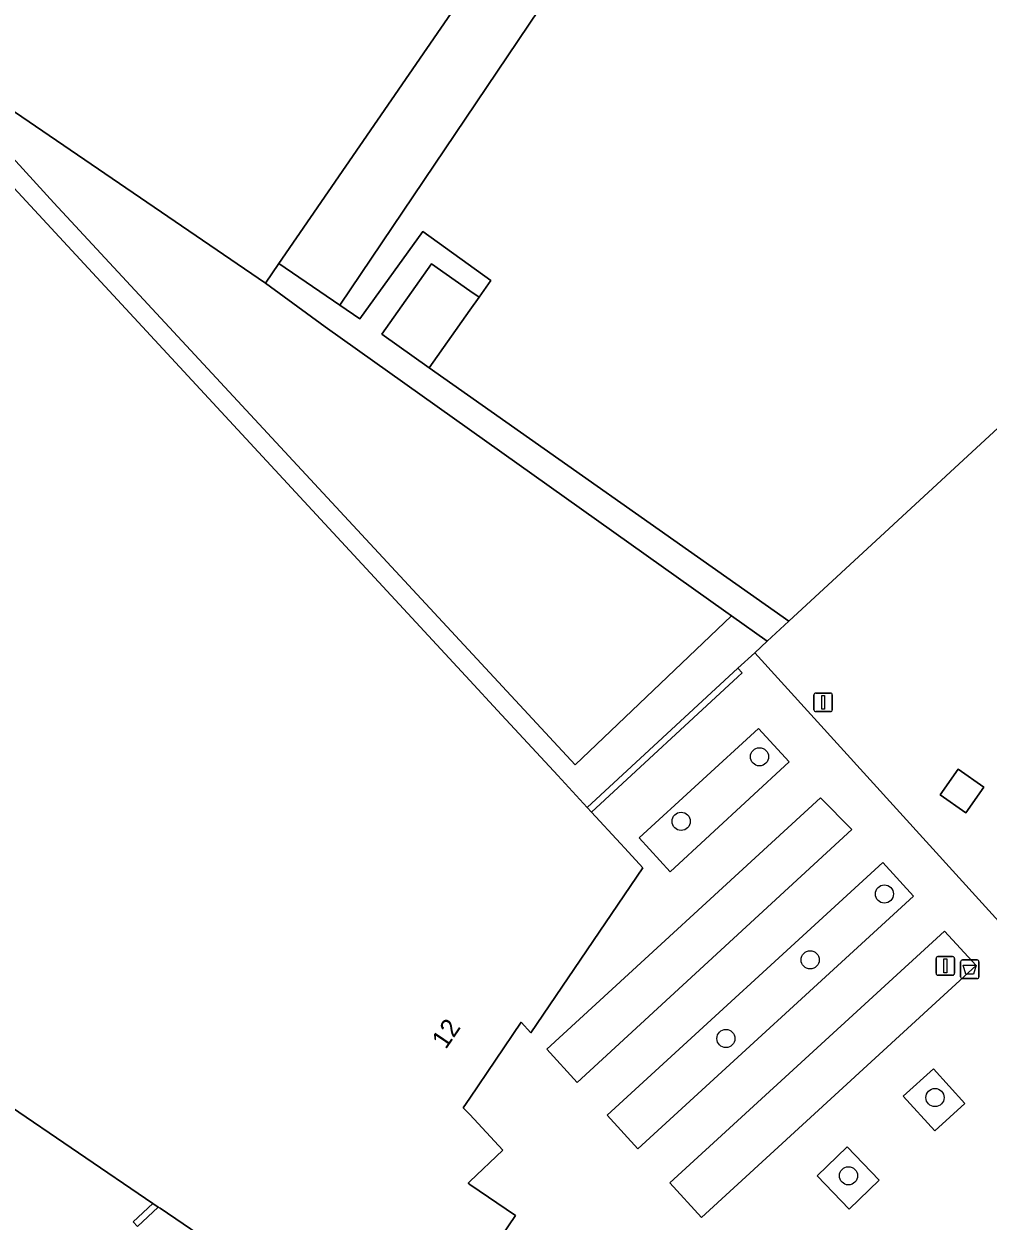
# Model space of a CAD drawing. Extents: x 157132 to 159279, y 384991 to 386650.
# Drawn here: x 158476 to 158527.9, y 385472.5 to 385536.9 of the extents above; entities that cross this region are included whole.
import ezdxf

# ---------------------------------------------------------------- set-up
doc = ezdxf.new("R2010")
doc.units = 0
for name, color, linetype in [('IMGEO_Afvalbak', 7, 'Continuous'), ('IMGEO_Boom', 7, 'Continuous'), ('IMGEO_Gemengd_bos', 7, 'Continuous'), ('IMGEO_Groenvoorziening', 7, 'Continuous'), ('IMGEO_Haag', 7, 'Continuous'), ('IMGEO_Hek', 7, 'Continuous'), ('IMGEO_Lichtmast', 7, 'Continuous'), ('IMGEO_Muur', 7, 'Continuous'), ('IMGEO_Pand', 7, 'Continuous'), ('IMGEO_Pand_nummerreeks', 7, 'Continuous'), ('IMGEO_Terreindeel_onvherhard', 7, 'Continuous'), ('IMGEO_Voetpad_open', 7, 'Continuous')]:
    doc.layers.add(name, color=color, linetype=linetype)

msp = doc.modelspace()

# ---------------------------------------------------------------- linework, layer by layer
at = {"layer": 'IMGEO_Afvalbak'}
for p, q in [((158526.419, 385485.668), (158526.419, 385486.468)), ((158526.419, 385486.468), (158526.419, 385485.668)), ((158526.519, 385486.568), (158527.309, 385486.568)), ((158527.309, 385486.568), (158526.519, 385486.568)), ((158527.409, 385486.468), (158527.409, 385485.668)), ((158527.409, 385485.668), (158527.409, 385486.468)), ((158527.309, 385485.568), (158526.519, 385485.568)), ((158526.519, 385485.568), (158527.309, 385485.568))]:
    msp.add_line(p, q, dxfattribs=at)
msp.add_lwpolyline([(158526.562, 385486.282), (158527.266, 385486.282), (158527.117, 385485.812), (158526.711, 385485.812), (158526.562, 385486.282)], dxfattribs=at)
for centre, start, end in [((158526.519, 385486.468), 90, 180), ((158526.519, 385486.468), 90, 180), ((158527.309, 385486.468), 0, 90), ((158527.309, 385486.468), 360, 90), ((158526.519, 385485.668), 180, 270), ((158526.519, 385485.668), 180, 270), ((158527.309, 385485.668), 270, 0), ((158527.309, 385485.668), 270, 0)]:
    msp.add_arc(centre, 0.1, start, end, dxfattribs=at)
at = {"layer": 'IMGEO_Boom'}
for centre in [(158515.593, 385497.506), (158511.376, 385494.032), (158522.32, 385490.12), (158518.322, 385486.575), (158513.786, 385482.342), (158525.042, 385479.165), (158520.385, 385474.954)]:
    msp.add_circle(centre, 0.489, dxfattribs=at)
at = {"layer": 'IMGEO_Gemengd_bos'}
for points in [[(158416.718, 385518.918), (158432.421, 385507.98), (158456.911, 385544.351), (158479.187, 385577.434), (158514.468, 385553.679), (158492.995, 385521.811), (158494.074, 385521.069), (158497.473, 385525.778), (158501.138, 385523.133), (158500.495, 385522.242), (158500, 385521.54), (158497.819, 385518.448), (158517.173, 385504.798), (158548.16, 385533.423), (158561.811, 385531.05), (158567.151, 385539), (158577.352, 385553.824), (158594.632, 385578.874), (158607.886, 385598.171), (158608.65, 385598.598), (158610.629, 385600.429)], [(158552.569, 385517.808), (158546.305, 385522.293), (158546.916, 385523.147), (158553.212, 385518.722), (158557.004, 385524.108), (158559.635, 385527.877), (158558.006, 385529.04), (158559.162, 385530.721), (158560.835, 385529.597), (158561.811, 385531.05), (158548.16, 385533.423), (158517.173, 385504.798), (158516.01, 385503.723), (158515.341, 385503.105), (158530.775, 385486.104), (158530.932, 385486.248)]]:
    msp.add_lwpolyline(points, dxfattribs=at)
msp.add_lwpolyline([(158526.705, 385494.493), (158525.323, 385495.454), (158526.284, 385496.837), (158527.666, 385495.876)], close=True, dxfattribs=at)
at = {"layer": 'IMGEO_Groenvoorziening'}
msp.add_lwpolyline([(158499.391, 385538.108), (158489.726, 385524.061), (158492.995, 385521.811), (158514.468, 385553.679)], dxfattribs=at)
for points in [[(158492.207, 385520.642), (158488.994, 385522.997), (158474.747, 385532.719), (158474.316, 385532.056), (158473.868, 385531.391), (158477.608, 385527.327), (158505.674, 385497.072), (158514.085, 385505.091), (158513.782, 385505.306)], [(158517.196, 385497.235), (158515.549, 385499.035), (158509.112, 385493.145), (158510.785, 385491.317)], [(158518.884, 385495.298), (158504.146, 385481.772), (158505.774, 385479.981), (158520.569, 385493.599)], [(158509.043, 385476.407), (158523.878, 385490.008), (158522.225, 385491.811), (158507.39, 385478.21)], [(158525.549, 385488.128), (158510.767, 385474.58), (158512.475, 385472.717), (158527.257, 385486.265)], [(158523.327, 385479.241), (158525.025, 385477.365), (158526.653, 385478.838), (158524.955, 385480.714)], [(158522.038, 385474.722), (158520.314, 385476.516), (158518.691, 385474.957), (158520.415, 385473.163)]]:
    msp.add_lwpolyline(points, close=True, dxfattribs=at)
at = {"layer": 'IMGEO_Haag'}
for points in [[(158523.327, 385479.241), (158525.025, 385477.365), (158526.653, 385478.838), (158524.955, 385480.714)], [(158522.038, 385474.722), (158520.314, 385476.516), (158518.691, 385474.957), (158520.415, 385473.163)]]:
    msp.add_lwpolyline(points, close=True, dxfattribs=at)
at = {"layer": 'IMGEO_Hek'}
for points in [[(158548.16, 385533.423), (158517.173, 385504.798), (158516.01, 385503.723)], [(158516.01, 385503.723), (158515.341, 385503.105)], [(158515.341, 385503.105), (158514.436, 385502.269)]]:
    msp.add_lwpolyline(points, dxfattribs=at)
at = {"layer": 'IMGEO_Lichtmast'}
for p, q in [((158518.522, 385500.037), (158518.522, 385500.837)), ((158518.522, 385500.837), (158518.522, 385500.037)), ((158518.622, 385500.937), (158519.412, 385500.937)), ((158519.412, 385500.937), (158518.622, 385500.937)), ((158519.512, 385500.837), (158519.512, 385500.037)), ((158519.512, 385500.037), (158519.512, 385500.837)), ((158519.412, 385499.937), (158518.622, 385499.937)), ((158518.622, 385499.937), (158519.412, 385499.937)), ((158525.102, 385485.852), (158525.102, 385486.652)), ((158525.102, 385486.652), (158525.102, 385485.852)), ((158525.202, 385486.752), (158525.992, 385486.752)), ((158525.992, 385486.752), (158525.202, 385486.752)), ((158526.092, 385486.652), (158526.092, 385485.852)), ((158526.092, 385485.852), (158526.092, 385486.652)), ((158525.992, 385485.752), (158525.202, 385485.752)), ((158525.202, 385485.752), (158525.992, 385485.752))]:
    msp.add_line(p, q, dxfattribs=at)
for points in [[(158518.942, 385500.812), (158519.092, 385500.812), (158519.092, 385500.062), (158518.942, 385500.062), (158518.942, 385500.812)], [(158525.522, 385486.627), (158525.672, 385486.627), (158525.672, 385485.877), (158525.522, 385485.877), (158525.522, 385486.627)]]:
    msp.add_lwpolyline(points, dxfattribs=at)
for centre, start, end in [((158518.622, 385500.837), 90, 180), ((158518.622, 385500.837), 90, 180), ((158519.412, 385500.837), 0, 90), ((158519.412, 385500.837), 360, 90), ((158518.622, 385500.037), 180, 270), ((158518.622, 385500.037), 180, 270), ((158519.412, 385500.037), 270, 0), ((158519.412, 385500.037), 270, 0), ((158525.202, 385486.652), 90, 180), ((158525.202, 385486.652), 90, 180), ((158525.992, 385486.652), 0, 90), ((158525.992, 385486.652), 360, 90), ((158525.202, 385485.852), 180, 270), ((158525.202, 385485.852), 180, 270), ((158525.992, 385485.852), 270, 0), ((158525.992, 385485.852), 270, 0)]:
    msp.add_arc(centre, 0.1, start, end, dxfattribs=at)
at = {"layer": 'IMGEO_Muur'}
for points in [[(158514.436, 385502.269), (158506.322, 385494.771)], [(158514.429, 385501.8), (158506.552, 385494.522)], [(158514.436, 385502.269), (158514.667, 385502.02), (158514.429, 385501.8)], [(158506.552, 385494.522), (158506.322, 385494.771)]]:
    msp.add_lwpolyline(points, dxfattribs=at)
msp.add_lwpolyline([(158482.939, 385473.468), (158481.877, 385472.482), (158482.108, 385472.232), (158483.227, 385473.272)], close=True, dxfattribs=at)
at = {"layer": 'IMGEO_Pand'}
for points in [[(158500, 385469.198), (158502.452, 385472.824), (158500, 385474.488), (158499.904, 385474.553), (158500, 385474.644), (158501.784, 385476.338), (158500, 385478.244), (158499.649, 385478.619), (158500, 385479.136), (158502.767, 385483.215), (158503.29, 385482.642), (158509.322, 385491.524), (158508.346, 385492.58), (158508.103, 385492.843), (158506.552, 385494.522), (158506.322, 385494.771), (158504.733, 385496.491), (158501.484, 385500), (158500, 385501.603), (158476.559, 385526.919), (158469.873, 385534.139)], [(158474.931, 385478.916), (158482.939, 385473.468), (158483.227, 385473.272), (158483.325, 385473.205), (158496.602, 385464.173)]]:
    msp.add_lwpolyline(points, dxfattribs=at)
for points in [[(158497.819, 385518.448), (158500, 385521.54), (158500.495, 385522.242), (158500, 385522.591), (158497.941, 385524.044), (158495.264, 385520.25)], [(158526.705, 385494.493), (158527.666, 385495.876), (158526.284, 385496.837), (158525.323, 385495.454)]]:
    msp.add_lwpolyline(points, close=True, dxfattribs=at)
at = {"layer": 'IMGEO_Terreindeel_onvherhard'}
msp.add_lwpolyline([(158469.587, 385558.365), (158459.253, 385543.292), (158473.559, 385533.529), (158474.747, 385532.719), (158488.994, 385522.997), (158489.726, 385524.061), (158499.391, 385538.108)], close=True, dxfattribs=at)
at = {"layer": 'IMGEO_Voetpad_open'}
for points in [[(158469.873, 385534.139), (158476.559, 385526.919), (158500, 385501.603), (158501.484, 385500), (158504.733, 385496.491), (158506.322, 385494.771), (158506.552, 385494.522), (158514.429, 385501.8), (158514.667, 385502.02), (158514.436, 385502.269), (158515.341, 385503.105), (158516.01, 385503.723), (158514.085, 385505.091), (158505.674, 385497.072), (158477.608, 385527.327), (158473.868, 385531.391)], [(158481.877, 385472.482), (158482.939, 385473.468), (158474.931, 385478.916), (158473.817, 385477.878), (158470.287, 385474.588), (158457.078, 385483.601), (158440.024, 385495.235), (158444.919, 385499.338), (158442.207, 385501.185), (158440.782, 385502.156), (158444.569, 385507.716), (158441.747, 385509.712), (158441.343, 385509.984), (158434.39, 385499.799), (158434.052, 385499.309), (158423.281, 385506.706), (158420.553, 385504.286), (158508.457, 385444.174)], [(158530.775, 385486.104), (158515.341, 385503.105), (158514.436, 385502.269), (158514.667, 385502.02), (158514.429, 385501.8), (158506.552, 385494.522), (158508.103, 385492.843), (158508.346, 385492.58), (158509.322, 385491.524), (158503.29, 385482.642), (158502.767, 385483.215), (158500, 385479.136), (158499.649, 385478.619), (158500, 385478.244), (158501.784, 385476.338), (158500, 385474.644), (158499.904, 385474.553), (158500, 385474.488), (158502.452, 385472.824), (158500, 385469.198)], [(158496.602, 385464.173), (158483.325, 385473.205), (158483.227, 385473.272), (158482.108, 385472.232)]]:
    msp.add_lwpolyline(points, dxfattribs=at)
for points in [[(158497.819, 385518.448), (158495.264, 385520.25), (158497.941, 385524.044), (158500, 385522.591), (158500.495, 385522.242), (158501.138, 385523.133), (158497.473, 385525.778), (158494.074, 385521.069), (158492.995, 385521.811), (158489.726, 385524.061), (158488.994, 385522.997), (158492.207, 385520.642), (158513.782, 385505.306), (158514.085, 385505.091), (158516.01, 385503.723), (158517.173, 385504.798)], [(158510.785, 385491.317), (158509.112, 385493.145), (158515.549, 385499.035), (158517.196, 385497.235)], [(158518.884, 385495.298), (158520.569, 385493.599), (158505.774, 385479.981), (158504.146, 385481.772)], [(158522.225, 385491.811), (158523.878, 385490.008), (158509.043, 385476.407), (158507.39, 385478.21)], [(158525.549, 385488.128), (158527.257, 385486.265), (158512.475, 385472.717), (158510.767, 385474.58)], [(158524.955, 385480.714), (158526.653, 385478.838), (158525.025, 385477.365), (158523.327, 385479.241)], [(158520.314, 385476.516), (158522.038, 385474.722), (158520.415, 385473.163), (158518.691, 385474.957)]]:
    msp.add_lwpolyline(points, close=True, dxfattribs=at)

# ---------------------------------------------------------------- texts
at = {"layer": 'IMGEO_Pand_nummerreeks'}
msp.add_text('12', height=1, rotation=55.8462, dxfattribs=at).set_placement((158498.708, 385481.721))

doc.saveas('drawing.dxf')
